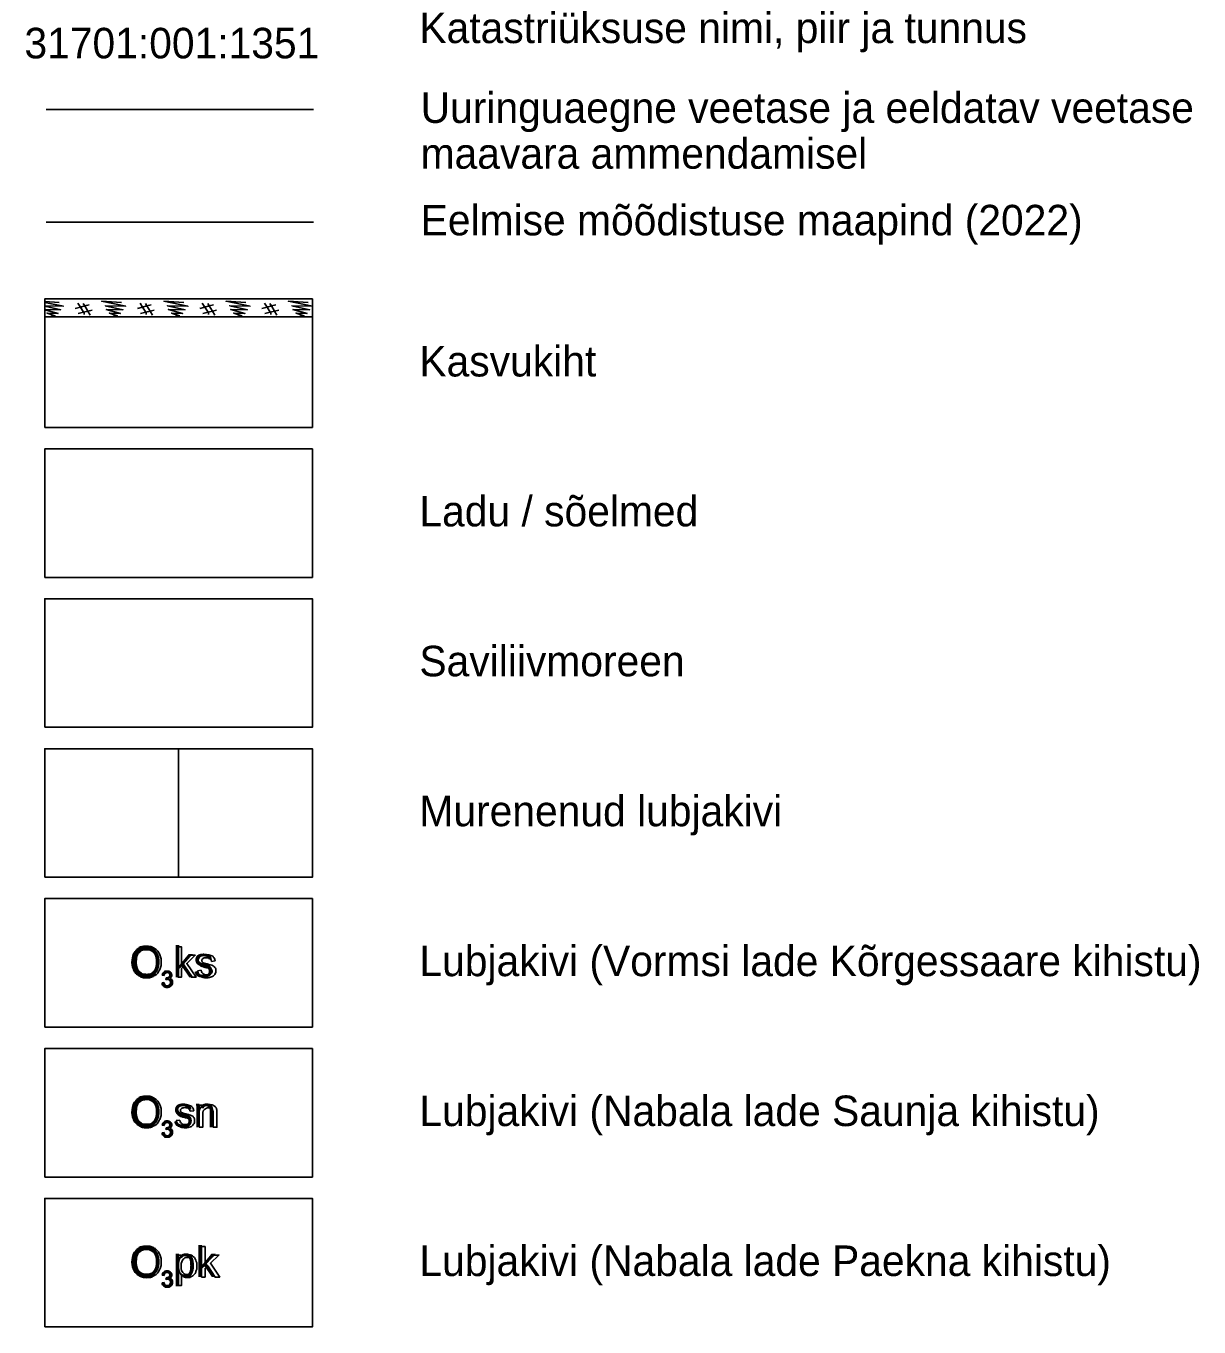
# Model space of a CAD drawing. Extents: x 532503 to 539665, y 6557663 to 6561526.
# Drawn here: x 538903.1 to 539122.3, y 6559686.9 to 6559929.8 of the extents above; entities that cross this region are included whole.
import ezdxf

# ---------------------------------------------------------------- set-up
doc = ezdxf.new("R2010")
doc.units = 0
for name, color, linetype in [('kataster', 7, 'Continuous'), ('Täide', 7, 'Continuous'), ('Veetase', 7, 'Continuous'), ('VORMISTUS', 7, 'Continuous')]:
    doc.layers.add(name, color=color, linetype=linetype)

msp = doc.modelspace()

# ---------------------------------------------------------------- linework, layer by layer
at = {"layer": 'Täide'}
for p, q in [((538906.63, 6559875.55), (538956.63, 6559875.55)), ((538956.63, 6559794.87), (538931.63, 6559794.87)), ((538931.63, 6559794.87), (538931.63, 6559770.87)), ((538956.63, 6559770.87), (538956.63, 6559794.87)), ((538906.63, 6559770.87), (538956.63, 6559770.87)), ((538931.63, 6559770.87), (538956.63, 6559770.87)), ((538906.63, 6559742.87), (538956.63, 6559742.87)), ((538906.63, 6559714.87), (538956.63, 6559714.87)), ((538906.63, 6559714.87), (538956.63, 6559714.87)), ((538906.63, 6559686.87), (538956.63, 6559686.87)), ((538906.63, 6559686.87), (538956.63, 6559686.87))]:
    msp.add_line(p, q, dxfattribs=at)
for points in [[(538909.34, 6559878.22), (538906.63, 6559878.37)], [(538906.63, 6559878.22), (538910.11, 6559877.51), (538906.63, 6559877.6)], [(538906.63, 6559877.53), (538909.6, 6559876.85), (538906.63, 6559876.9)], [(538906.63, 6559876.86), (538909.12, 6559876.17), (538907.06, 6559876.24), (538908.53, 6559875.73), (538907.36, 6559875.55)], [(538913.81, 6559878.03), (538914.09, 6559877.56), (538913.27, 6559877.34), (538912.31, 6559877.09)], [(538912.8, 6559878.08), (538913.27, 6559877.34), (538913.88, 6559876.39), (538912.87, 6559876.16)], [(538913.96, 6559875.96), (538913.96, 6559876.26), (538913.88, 6559876.39), (538914.69, 6559876.58), (538914.09, 6559877.56), (538914.9, 6559877.77)], [(538920.97, 6559878.22), (538917.25, 6559878.42), (538921.74, 6559877.51), (538917.92, 6559877.61), (538921.22, 6559876.85), (538918.1, 6559876.9), (538920.75, 6559876.17), (538918.69, 6559876.24), (538920.16, 6559875.73), (538918.99, 6559875.55)], [(538925.44, 6559878.03), (538925.72, 6559877.56), (538924.9, 6559877.34), (538923.94, 6559877.09)], [(538924.43, 6559878.08), (538924.9, 6559877.34), (538925.51, 6559876.39), (538924.5, 6559876.16)], [(538925.59, 6559875.96), (538925.59, 6559876.26), (538925.51, 6559876.39), (538926.32, 6559876.58), (538925.72, 6559877.56), (538926.53, 6559877.77)], [(538932.6, 6559878.22), (538928.88, 6559878.42), (538933.37, 6559877.51), (538929.55, 6559877.61), (538932.85, 6559876.85), (538929.73, 6559876.9), (538932.38, 6559876.17), (538930.32, 6559876.24), (538931.79, 6559875.73), (538930.62, 6559875.55)], [(538937.07, 6559878.03), (538937.35, 6559877.56), (538936.53, 6559877.34), (538935.57, 6559877.09)], [(538936.06, 6559878.08), (538936.53, 6559877.34), (538937.14, 6559876.39), (538936.13, 6559876.16)], [(538937.22, 6559875.96), (538937.22, 6559876.26), (538937.14, 6559876.39), (538937.95, 6559876.58), (538937.35, 6559877.56), (538938.16, 6559877.77)], [(538944.22, 6559878.22), (538940.51, 6559878.42), (538945, 6559877.51), (538941.18, 6559877.61), (538944.48, 6559876.85), (538941.36, 6559876.9), (538944.01, 6559876.17), (538941.95, 6559876.24), (538943.42, 6559875.73), (538942.24, 6559875.55)], [(538948.7, 6559878.03), (538948.98, 6559877.56), (538948.16, 6559877.34), (538947.2, 6559877.09)], [(538947.69, 6559878.08), (538948.16, 6559877.34), (538948.77, 6559876.39), (538947.76, 6559876.16)], [(538948.85, 6559875.96), (538948.85, 6559876.26), (538948.77, 6559876.39), (538949.58, 6559876.58), (538948.98, 6559877.56), (538949.79, 6559877.77)], [(538955.85, 6559878.22), (538952.14, 6559878.42), (538956.63, 6559877.51), (538952.81, 6559877.61), (538956.11, 6559876.85), (538952.99, 6559876.9), (538955.64, 6559876.17), (538953.58, 6559876.24), (538955.05, 6559875.73), (538953.87, 6559875.55)], [(538915.46, 6559876.75), (538914.69, 6559876.58), (538915.12, 6559875.86)], [(538927.09, 6559876.75), (538926.32, 6559876.58), (538926.75, 6559875.86)], [(538938.72, 6559876.75), (538937.95, 6559876.58), (538938.38, 6559875.86)], [(538950.35, 6559876.75), (538949.58, 6559876.58), (538950.01, 6559875.86)], [(538906.63, 6559826.87), (538956.63, 6559826.87), (538956.63, 6559850.87)], [(538956.63, 6559850.87), (538906.63, 6559850.87), (538906.63, 6559826.87)], [(538906.63, 6559798.87), (538956.63, 6559798.87), (538956.63, 6559822.87), (538906.63, 6559822.87), (538906.63, 6559798.87)], [(538956.63, 6559770.87), (538956.63, 6559794.87), (538906.63, 6559794.87), (538906.63, 6559770.87)], [(538956.63, 6559742.87), (538956.63, 6559766.87), (538906.63, 6559766.87), (538906.63, 6559742.87)], [(538906.63, 6559714.87), (538956.63, 6559714.87), (538956.63, 6559738.87), (538906.63, 6559738.87), (538906.63, 6559714.87)], [(538956.63, 6559714.87), (538956.63, 6559738.87), (538906.63, 6559738.87), (538906.63, 6559714.87)], [(538956.63, 6559714.87), (538956.63, 6559738.87), (538906.63, 6559738.87), (538906.63, 6559714.87)], [(538906.63, 6559686.87), (538956.63, 6559686.87), (538956.63, 6559710.87), (538906.63, 6559710.87), (538906.63, 6559686.87)], [(538956.63, 6559686.87), (538956.63, 6559710.87), (538906.63, 6559710.87), (538906.63, 6559686.87)], [(538956.63, 6559686.87), (538956.63, 6559710.87), (538906.63, 6559710.87), (538906.63, 6559686.87)]]:
    msp.add_lwpolyline(points, dxfattribs=at)
for points in [[(538906.63, 6559770.87), (538931.63, 6559770.87), (538931.63, 6559794.87), (538906.63, 6559794.87)], [(538906.63, 6559742.87), (538956.63, 6559742.87), (538956.63, 6559766.87), (538906.63, 6559766.87)]]:
    msp.add_lwpolyline(points, close=True, dxfattribs=at)
at = {"layer": 'Veetase'}
for p, q in [((538906.86, 6559914.22), (538956.86, 6559914.22)), ((538906.86, 6559893.22), (538956.86, 6559893.22))]:
    msp.add_line(p, q, dxfattribs=at)
at = {"layer": 'VORMISTUS'}
for p, q in [((538956.63, 6559850.87), (538906.63, 6559850.87)), ((538906.63, 6559850.87), (538906.63, 6559826.87)), ((538956.63, 6559826.87), (538956.63, 6559850.87)), ((538906.63, 6559826.87), (538956.63, 6559826.87))]:
    msp.add_line(p, q, dxfattribs=at)
for points in [[(538906.63, 6559854.87), (538956.63, 6559854.87), (538956.63, 6559878.87), (538906.63, 6559878.87)], [(538906.63, 6559826.87), (538956.63, 6559826.87), (538956.63, 6559850.87), (538906.63, 6559850.87)], [(538906.63, 6559798.87), (538956.63, 6559798.87), (538956.63, 6559822.87), (538906.63, 6559822.87)]]:
    msp.add_lwpolyline(points, close=True, dxfattribs=at)
for points in [[(538906.63, 6559826.87), (538956.63, 6559826.87), (538956.63, 6559850.87), (538906.63, 6559850.87), (538906.63, 6559826.87)], [(538906.63, 6559770.87), (538956.63, 6559770.87), (538956.63, 6559794.87), (538906.63, 6559794.87), (538906.63, 6559770.87)], [(538906.63, 6559742.87), (538956.63, 6559742.87), (538956.63, 6559766.87), (538906.63, 6559766.87), (538906.63, 6559742.87)], [(538931.46, 6559752.18), (538931.46, 6559757.88), (538932.16, 6559757.88), (538932.16, 6559754.63), (538933.82, 6559756.31), (538934.73, 6559756.31), (538933.15, 6559754.77), (538934.89, 6559752.18), (538934.03, 6559752.18), (538932.65, 6559754.29), (538932.16, 6559753.81), (538932.16, 6559752.18), (538931.46, 6559752.18)], [(538935.16, 6559753.41), (538935.85, 6559753.52)], [(538938.44, 6559755.24), (538937.76, 6559755.15)], [(538928.54, 6559751.13), (538928.9, 6559751.18)], [(538928.94, 6559752.51), (538928.57, 6559752.57)], [(538929.26, 6559751.76), (538929.3, 6559752.08)], [(538906.63, 6559714.87), (538956.63, 6559714.87), (538956.63, 6559738.87), (538906.63, 6559738.87), (538906.63, 6559714.87)], [(538934.46, 6559727.24), (538933.77, 6559727.15)], [(538935.45, 6559724.18), (538935.45, 6559728.31), (538936.08, 6559728.31), (538936.08, 6559727.72)], [(538936.15, 6559726.43), (538936.15, 6559724.18), (538935.45, 6559724.18)], [(538938.8, 6559726.72), (538938.8, 6559724.18), (538938.1, 6559724.18), (538938.1, 6559726.69)], [(538928.94, 6559724.51), (538928.57, 6559724.57)], [(538929.26, 6559723.76), (538929.3, 6559724.08)], [(538931.18, 6559725.41), (538931.87, 6559725.52)], [(538928.54, 6559723.13), (538928.91, 6559723.18)], [(538906.63, 6559686.87), (538956.63, 6559686.87), (538956.63, 6559710.87), (538906.63, 6559710.87), (538906.63, 6559686.87)], [(538935.89, 6559696.18), (538935.89, 6559701.88), (538936.59, 6559701.88), (538936.59, 6559698.63), (538938.25, 6559700.31), (538939.16, 6559700.31), (538937.58, 6559698.77), (538939.32, 6559696.18), (538938.45, 6559696.18), (538937.08, 6559698.29), (538936.59, 6559697.81), (538936.59, 6559696.18), (538935.89, 6559696.18)], [(538931.46, 6559694.6), (538931.46, 6559700.31), (538932.1, 6559700.31), (538932.1, 6559699.77)], [(538928.54, 6559695.13), (538928.91, 6559695.18)], [(538928.94, 6559696.51), (538928.57, 6559696.57)], [(538929.26, 6559695.76), (538929.3, 6559696.08)], [(538932.16, 6559696.6), (538932.16, 6559694.6), (538931.46, 6559694.6)]]:
    msp.add_lwpolyline(points, dxfattribs=at)
for points in [[(538922.92, 6559754.95), (538922.92, 6559756.37), (538923.68, 6559757.17), (538924.44, 6559757.98), (538925.65, 6559757.98), (538926.44, 6559757.98), (538927.07, 6559757.6), (538927.7, 6559757.22), (538928.04, 6559756.55), (538928.37, 6559755.87), (538928.37, 6559755.02), (538928.37, 6559754.15), (538928.02, 6559753.47), (538927.67, 6559752.78), (538927.03, 6559752.43), (538926.38, 6559752.08), (538925.64, 6559752.08), (538924.84, 6559752.08), (538924.2, 6559752.47), (538923.57, 6559752.86), (538923.24, 6559753.53), (538922.92, 6559754.2), (538922.92, 6559754.95)], [(538923.69, 6559754.94), (538923.69, 6559753.91), (538924.25, 6559753.32), (538924.8, 6559752.73), (538925.64, 6559752.73), (538926.49, 6559752.73), (538927.04, 6559753.33), (538927.59, 6559753.93), (538927.59, 6559755.02), (538927.59, 6559755.72), (538927.35, 6559756.24), (538927.12, 6559756.76), (538926.67, 6559757.04), (538926.21, 6559757.33), (538925.65, 6559757.33), (538924.85, 6559757.33), (538924.27, 6559756.78), (538923.69, 6559756.23), (538923.69, 6559754.94)], [(538937.76, 6559755.15), (538937.71, 6559755.47), (538937.49, 6559755.65), (538937.26, 6559755.83), (538936.85, 6559755.83), (538936.37, 6559755.83), (538936.16, 6559755.67), (538935.96, 6559755.51), (538935.96, 6559755.29), (538935.96, 6559755.16), (538936.04, 6559755.05), (538936.13, 6559754.93), (538936.31, 6559754.86), (538936.42, 6559754.82), (538936.93, 6559754.68), (538937.67, 6559754.48), (538937.97, 6559754.36), (538938.26, 6559754.23), (538938.43, 6559753.99), (538938.6, 6559753.75), (538938.6, 6559753.39), (538938.6, 6559753.04), (538938.39, 6559752.73), (538938.19, 6559752.42), (538937.8, 6559752.25), (538937.42, 6559752.09), (538936.93, 6559752.09), (538936.13, 6559752.09), (538935.7, 6559752.42), (538935.28, 6559752.75), (538935.16, 6559753.41)], [(538935.85, 6559753.52), (538935.91, 6559753.1), (538936.18, 6559752.88), (538936.45, 6559752.66), (538936.93, 6559752.66), (538937.41, 6559752.66), (538937.64, 6559752.86), (538937.88, 6559753.05), (538937.88, 6559753.32), (538937.88, 6559753.55), (538937.67, 6559753.69), (538937.53, 6559753.78), (538936.95, 6559753.93), (538936.18, 6559754.12), (538935.89, 6559754.26), (538935.59, 6559754.41), (538935.43, 6559754.66), (538935.28, 6559754.91), (538935.28, 6559755.21), (538935.28, 6559755.49), (538935.41, 6559755.72), (538935.53, 6559755.96), (538935.75, 6559756.11), (538935.91, 6559756.23), (538936.2, 6559756.32), (538936.48, 6559756.4), (538936.8, 6559756.4), (538937.29, 6559756.4), (538937.66, 6559756.26), (538938.03, 6559756.12), (538938.2, 6559755.88), (538938.38, 6559755.64), (538938.44, 6559755.24)], [(538928.57, 6559752.57), (538928.64, 6559752.94), (538928.88, 6559753.15), (538929.12, 6559753.35), (538929.48, 6559753.35), (538929.72, 6559753.35), (538929.93, 6559753.25), (538930.13, 6559753.14), (538930.24, 6559752.96), (538930.35, 6559752.78), (538930.35, 6559752.57), (538930.35, 6559752.38), (538930.25, 6559752.22), (538930.15, 6559752.06), (538929.94, 6559751.97), (538930.21, 6559751.9), (538930.35, 6559751.71), (538930.5, 6559751.52), (538930.5, 6559751.23), (538930.5, 6559750.83), (538930.21, 6559750.56), (538929.93, 6559750.29), (538929.49, 6559750.29), (538929.09, 6559750.29), (538928.83, 6559750.52), (538928.57, 6559750.76), (538928.54, 6559751.13)], [(538929.3, 6559752.08), (538929.34, 6559752.08), (538929.36, 6559752.08), (538929.6, 6559752.08), (538929.79, 6559752.2), (538929.97, 6559752.32), (538929.97, 6559752.58), (538929.97, 6559752.78), (538929.84, 6559752.92), (538929.7, 6559753.05), (538929.48, 6559753.05), (538929.27, 6559753.05), (538929.13, 6559752.91), (538928.98, 6559752.78), (538928.94, 6559752.51)], [(538928.9, 6559751.18), (538928.97, 6559750.87), (538929.12, 6559750.73), (538929.27, 6559750.59), (538929.49, 6559750.59), (538929.75, 6559750.59), (538929.93, 6559750.77), (538930.11, 6559750.95), (538930.11, 6559751.22), (538930.11, 6559751.47), (538929.94, 6559751.64), (538929.78, 6559751.8), (538929.52, 6559751.8), (538929.42, 6559751.8), (538929.26, 6559751.76)], [(538922.92, 6559726.95), (538922.92, 6559728.37), (538923.68, 6559729.17), (538924.44, 6559729.98), (538925.65, 6559729.98), (538926.44, 6559729.98), (538927.07, 6559729.6), (538927.7, 6559729.22), (538928.04, 6559728.55), (538928.37, 6559727.87), (538928.37, 6559727.02), (538928.37, 6559726.15), (538928.02, 6559725.47), (538927.67, 6559724.78), (538927.03, 6559724.43), (538926.39, 6559724.08), (538925.64, 6559724.08), (538924.84, 6559724.08), (538924.2, 6559724.47), (538923.57, 6559724.86), (538923.24, 6559725.53), (538922.92, 6559726.2), (538922.92, 6559726.95)], [(538923.69, 6559726.94), (538923.69, 6559725.91), (538924.25, 6559725.32), (538924.8, 6559724.73), (538925.64, 6559724.73), (538926.49, 6559724.73), (538927.04, 6559725.33), (538927.59, 6559725.93), (538927.59, 6559727.02), (538927.59, 6559727.72), (538927.36, 6559728.24), (538927.12, 6559728.76), (538926.67, 6559729.04), (538926.21, 6559729.33), (538925.65, 6559729.33), (538924.85, 6559729.33), (538924.27, 6559728.78), (538923.69, 6559728.23), (538923.69, 6559726.94)], [(538933.77, 6559727.15), (538933.73, 6559727.47), (538933.5, 6559727.65), (538933.28, 6559727.83), (538932.87, 6559727.83), (538932.39, 6559727.83), (538932.18, 6559727.67), (538931.98, 6559727.51), (538931.98, 6559727.29), (538931.98, 6559727.16), (538932.06, 6559727.05), (538932.15, 6559726.93), (538932.33, 6559726.86), (538932.43, 6559726.82), (538932.95, 6559726.68), (538933.69, 6559726.48), (538933.99, 6559726.36), (538934.28, 6559726.23), (538934.45, 6559725.99), (538934.62, 6559725.75), (538934.62, 6559725.39), (538934.62, 6559725.04), (538934.41, 6559724.73), (538934.21, 6559724.42), (538933.82, 6559724.25), (538933.44, 6559724.09), (538932.95, 6559724.09), (538932.14, 6559724.09), (538931.72, 6559724.42), (538931.3, 6559724.75), (538931.18, 6559725.41)], [(538931.87, 6559725.52), (538931.93, 6559725.1), (538932.2, 6559724.88), (538932.46, 6559724.66), (538932.94, 6559724.66), (538933.43, 6559724.66), (538933.66, 6559724.86), (538933.9, 6559725.05), (538933.9, 6559725.32), (538933.9, 6559725.55), (538933.69, 6559725.69), (538933.54, 6559725.78), (538932.97, 6559725.93), (538932.2, 6559726.12), (538931.9, 6559726.26), (538931.61, 6559726.41), (538931.45, 6559726.66), (538931.3, 6559726.91), (538931.3, 6559727.21), (538931.3, 6559727.49), (538931.42, 6559727.72), (538931.55, 6559727.96), (538931.77, 6559728.11), (538931.93, 6559728.23), (538932.21, 6559728.32), (538932.5, 6559728.4), (538932.82, 6559728.4), (538933.31, 6559728.4), (538933.68, 6559728.26), (538934.04, 6559728.12), (538934.22, 6559727.88), (538934.39, 6559727.64), (538934.46, 6559727.24)], [(538936.08, 6559727.72), (538936.53, 6559728.4), (538937.39, 6559728.4), (538937.76, 6559728.4), (538938.08, 6559728.27), (538938.39, 6559728.13), (538938.54, 6559727.91), (538938.7, 6559727.7), (538938.76, 6559727.4), (538938.8, 6559727.2), (538938.8, 6559726.72)], [(538938.1, 6559726.69), (538938.1, 6559727.11), (538938.02, 6559727.33), (538937.94, 6559727.54), (538937.73, 6559727.66), (538937.52, 6559727.79), (538937.24, 6559727.79), (538936.8, 6559727.79), (538936.47, 6559727.51), (538936.15, 6559727.22), (538936.15, 6559726.43)], [(538928.57, 6559724.57), (538928.64, 6559724.94), (538928.88, 6559725.15), (538929.12, 6559725.35), (538929.48, 6559725.35), (538929.72, 6559725.35), (538929.93, 6559725.25), (538930.14, 6559725.14), (538930.25, 6559724.96), (538930.36, 6559724.78), (538930.36, 6559724.57), (538930.36, 6559724.38), (538930.25, 6559724.22), (538930.15, 6559724.06), (538929.94, 6559723.97), (538930.21, 6559723.9), (538930.36, 6559723.71), (538930.5, 6559723.52), (538930.5, 6559723.23), (538930.5, 6559722.83), (538930.22, 6559722.56), (538929.93, 6559722.29), (538929.49, 6559722.29), (538929.1, 6559722.29), (538928.84, 6559722.52), (538928.57, 6559722.76), (538928.54, 6559723.13)], [(538928.91, 6559723.18), (538928.97, 6559722.87), (538929.12, 6559722.73), (538929.27, 6559722.59), (538929.49, 6559722.59), (538929.75, 6559722.59), (538929.93, 6559722.77), (538930.11, 6559722.95), (538930.11, 6559723.22), (538930.11, 6559723.47), (538929.95, 6559723.64), (538929.78, 6559723.8), (538929.52, 6559723.8), (538929.42, 6559723.8), (538929.26, 6559723.76)], [(538929.3, 6559724.08), (538929.34, 6559724.08), (538929.36, 6559724.08), (538929.6, 6559724.08), (538929.79, 6559724.2), (538929.98, 6559724.32), (538929.98, 6559724.58), (538929.98, 6559724.78), (538929.84, 6559724.92), (538929.7, 6559725.05), (538929.48, 6559725.05), (538929.27, 6559725.05), (538929.13, 6559724.91), (538928.98, 6559724.78), (538928.94, 6559724.51)], [(538922.92, 6559698.95), (538922.92, 6559700.37), (538923.68, 6559701.17), (538924.44, 6559701.98), (538925.65, 6559701.98), (538926.44, 6559701.98), (538927.07, 6559701.6), (538927.7, 6559701.22), (538928.04, 6559700.55), (538928.37, 6559699.87), (538928.37, 6559699.02), (538928.37, 6559698.15), (538928.02, 6559697.47), (538927.67, 6559696.78), (538927.03, 6559696.43), (538926.39, 6559696.08), (538925.64, 6559696.08), (538924.84, 6559696.08), (538924.2, 6559696.47), (538923.57, 6559696.86), (538923.24, 6559697.53), (538922.92, 6559698.2), (538922.92, 6559698.95)], [(538923.69, 6559698.94), (538923.69, 6559697.91), (538924.25, 6559697.32), (538924.8, 6559696.73), (538925.64, 6559696.73), (538926.49, 6559696.73), (538927.04, 6559697.33), (538927.59, 6559697.93), (538927.59, 6559699.02), (538927.59, 6559699.72), (538927.36, 6559700.24), (538927.12, 6559700.76), (538926.67, 6559701.04), (538926.21, 6559701.33), (538925.65, 6559701.33), (538924.85, 6559701.33), (538924.27, 6559700.78), (538923.69, 6559700.23), (538923.69, 6559698.94)], [(538932.1, 6559699.77), (538932.33, 6559700.08), (538932.61, 6559700.24), (538932.89, 6559700.4), (538933.3, 6559700.4), (538933.83, 6559700.4), (538934.23, 6559700.13), (538934.64, 6559699.86), (538934.84, 6559699.36), (538935.05, 6559698.86), (538935.05, 6559698.27), (538935.05, 6559697.64), (538934.82, 6559697.13), (538934.59, 6559696.63), (538934.16, 6559696.36), (538933.73, 6559696.09), (538933.25, 6559696.09), (538932.9, 6559696.09), (538932.62, 6559696.23), (538932.34, 6559696.38), (538932.16, 6559696.6)], [(538932.1, 6559698.22), (538932.1, 6559697.42), (538932.42, 6559697.04), (538932.74, 6559696.66), (538933.2, 6559696.66), (538933.66, 6559696.66), (538933.99, 6559697.05), (538934.33, 6559697.45), (538934.33, 6559698.28), (538934.33, 6559699.07), (538934, 6559699.46), (538933.68, 6559699.85), (538933.23, 6559699.85), (538932.78, 6559699.85), (538932.44, 6559699.43), (538932.1, 6559699.02), (538932.1, 6559698.22)], [(538928.57, 6559696.57), (538928.64, 6559696.94), (538928.88, 6559697.15), (538929.12, 6559697.35), (538929.48, 6559697.35), (538929.72, 6559697.35), (538929.93, 6559697.25), (538930.14, 6559697.14), (538930.25, 6559696.96), (538930.36, 6559696.78), (538930.36, 6559696.57), (538930.36, 6559696.38), (538930.25, 6559696.22), (538930.15, 6559696.06), (538929.94, 6559695.97), (538930.21, 6559695.9), (538930.36, 6559695.71), (538930.5, 6559695.52), (538930.5, 6559695.23), (538930.5, 6559694.83), (538930.22, 6559694.56), (538929.93, 6559694.29), (538929.49, 6559694.29), (538929.1, 6559694.29), (538928.84, 6559694.52), (538928.57, 6559694.76), (538928.54, 6559695.13)], [(538929.3, 6559696.08), (538929.34, 6559696.08), (538929.36, 6559696.08), (538929.6, 6559696.08), (538929.79, 6559696.2), (538929.98, 6559696.32), (538929.98, 6559696.58), (538929.98, 6559696.78), (538929.84, 6559696.92), (538929.7, 6559697.05), (538929.48, 6559697.05), (538929.27, 6559697.05), (538929.13, 6559696.91), (538928.98, 6559696.78), (538928.94, 6559696.51)], [(538928.91, 6559695.18), (538928.97, 6559694.87), (538929.12, 6559694.73), (538929.27, 6559694.59), (538929.49, 6559694.59), (538929.75, 6559694.59), (538929.93, 6559694.77), (538930.11, 6559694.95), (538930.11, 6559695.22), (538930.11, 6559695.47), (538929.95, 6559695.64), (538929.78, 6559695.8), (538929.52, 6559695.8), (538929.42, 6559695.8), (538929.26, 6559695.76)]]:
    msp.add_open_spline(points, degree=3, dxfattribs=at)

# ---------------------------------------------------------------- texts
at = {"layer": 'kataster'}
msp.add_text('31701:001:1351', height=5.7, dxfattribs=at).set_placement((538902.82, 6559923.8))
at = {"layer": 'VORMISTUS'}
for s, height, p in [('Katastriüksuse nimi, piir ja tunnus', 5.7, (538976.63, 6559926.65)), ('Uuringuaegne veetase ja eeldatav veetase', 5.7, (538976.86, 6559911.74)), ('maavara ammendamisel', 5.7, (538976.86, 6559903.19)), ('Eelmise mõõdistuse maapind (2022)', 5.7, (538976.86, 6559890.74)), ('Kasvukiht', 5.7, (538976.63, 6559864.39)), ('Ladu / sõelmed', 5.7, (538976.63, 6559836.39)), ('Saviliivmoreen', 5.7, (538976.63, 6559808.39)), ('Murenenud lubjakivi', 5.7, (538976.63, 6559780.39)), ('O ks', 5.7, (538922.53, 6559752.18)), ('Lubjakivi (Vormsi lade Kõrgessaare kihistu)', 5.7, (538976.63, 6559752.39)), ('3', 3, (538928.36, 6559750.34)), ('O sn', 5.7, (538922.53, 6559724.18)), ('Lubjakivi (Nabala lade Saunja kihistu)', 5.7, (538976.63, 6559724.39)), ('3', 3, (538928.36, 6559722.34)), ('O pk', 5.7, (538922.53, 6559696.18)), ('Lubjakivi (Nabala lade Paekna kihistu)', 5.7, (538976.63, 6559696.39)), ('3', 3, (538928.36, 6559694.34))]:
    msp.add_text(s, height=height, dxfattribs=at).set_placement(p)

doc.saveas('drawing.dxf')
